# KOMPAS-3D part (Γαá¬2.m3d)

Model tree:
1. Эскиз:1
2. Операция выдавливания:2
     Расстояние 1 = 3.5; Расстояние 2 = 3.5
3. Скругление:3
     Радиус = 5
4. Скругление:4
     Радиус = 0.1
5. Скругление:5
     Радиус = 0.1
6. Эскиз:3
7. Эскиз:4
8. Операция выдавливания:3
     Расстояние 1 = 9; Угол 1 = 6.5; Расстояние 2 = 3.5
9. Эскиз:5
10. Вырезать элемент выдавливания:3
     Расстояние 1 = 10
11. Скругление:7
     Радиус = 1
12. Скругление:8
     Радиус = 1
13. Скругление:9
     Радиус = 1
14. Скругление:10
     Радиус = 0.1
15. Скругление:11
     Радиус = 0.1
16. Вырезать элемент выдавливания:4
     Расстояние 1 = 10

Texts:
  трак2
